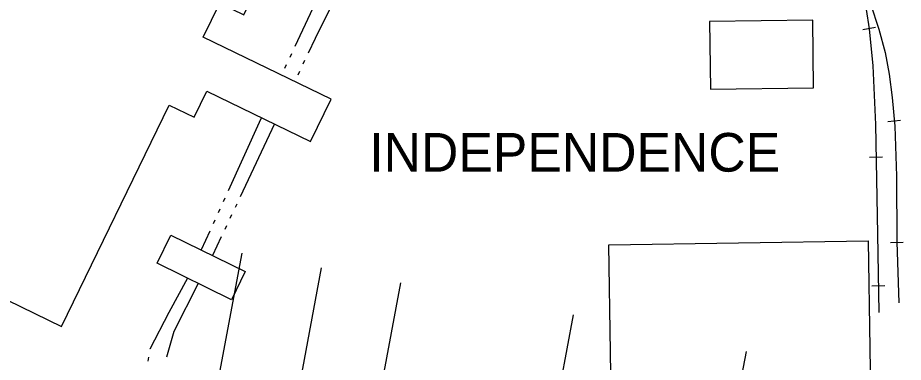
# Model space of a CAD drawing. Extents: x -25029 to 2274964, y -81170 to 687028.
# Drawn here: x -6125 to -5438, y -66014 to -65746 of the extents above; entities that cross this region are included whole.
import ezdxf

# ---------------------------------------------------------------- set-up
doc = ezdxf.new("R2010")
doc.units = 0
for name, color, linetype in [('BD_X_Canopy', 7, 'Continuous'), ('BLDG', 7, 'Continuous'), ('BRIDGE', 7, 'Continuous'), ('CITY-NAME', 7, 'Continuous'), ('RR', 7, 'Continuous'), ('TR_Turning_Path1', 7, 'Continuous'), ('WATER', 7, 'Continuous')]:
    doc.layers.add(name, color=color, linetype=linetype)

msp = doc.modelspace()

# ---------------------------------------------------------------- linework, layer by layer
at = {"layer": 'BD_X_Canopy'}
for p, q in [((-6013.27, -66266.31), (-5950.67, -65929.34)), ((-5951.75, -66277.75), (-5889.14, -65940.78)), ((-5890.22, -66289.19), (-5827.62, -65952.21)), ((-5756.09, -66314.07), (-5693.49, -65977.12))]:
    msp.add_line(p, q, dxfattribs=at)
at = {"layer": 'BLDG'}
for points in [[(-6090.73, -65986.09), (-6007.19, -65814.3), (-5987.85, -65823.7), (-5977.96, -65803.38), (-5897.49, -65842.51), (-5881.58, -65809.79), (-5980.73, -65761.57), (-5967.91, -65735.22), (-5949.36, -65744.24), (-5936.78, -65718.36), (-5956.11, -65708.96), (-5859.01, -65509.31), (-5928.1, -65475.71), (-5941.2, -65502.64), (-5964.09, -65491.51), (-5950.98, -65464.53), (-6027.49, -65427.32), (-6040.7, -65454.48), (-6052.09, -65448.94), (-6270.74, -65898.54)], [(-5587.38, -65801.96), (-5507.31, -65800.9), (-5508.01, -65748.34), (-5588.08, -65749.4)], [(-5464.9, -65919.57), (-5461.02, -66169.84), (-5662.41, -66172.96), (-5666.28, -65922.69)]]:
    msp.add_lwpolyline(points, close=True, dxfattribs=at)
at = {"layer": 'BRIDGE'}
msp.add_lwpolyline([(-6005.77, -65915.18), (-5948.18, -65943.59), (-5958.94, -65965.4), (-6016.53, -65937)], close=True, dxfattribs=at)
at = {"layer": 'RR'}
for p, q in [((-5469.15, -65755.55), (-5459.29, -65753.89)), ((-5449.78, -65826.93), (-5439.82, -65826.06)), ((-5463.92, -65854.64), (-5453.92, -65854.44)), ((-5447.76, -65920.93), (-5437.77, -65920.6)), ((-5462.13, -65954.6), (-5452.13, -65954.45))]:
    msp.add_line(p, q, dxfattribs=at)
for points in [[(-5509.4, -65612.28), (-5501.45, -65629.95), (-5492.99, -65649.66), (-5485.66, -65667.72), (-5479.77, -65686.65), (-5474.44, -65706.99), (-5470.36, -65723.98), (-5466.67, -65740.15), (-5464.18, -65754.94), (-5461.44, -65783.88), (-5459.43, -65829.39), (-5457.71, -65914.54), (-5456.83, -65975.4)], [(-5479.07, -65689.92), (-5470.58, -65712.22), (-5463.27, -65735.58), (-5456.64, -65755.33), (-5451.89, -65773.49), (-5448.62, -65790.34), (-5446.39, -65808.39), (-5444.43, -65830.72), (-5442.93, -65869.56), (-5442.78, -65920.48), (-5441.21, -65967.89)]]:
    msp.add_lwpolyline(points, dxfattribs=at)
at = {"layer": 'TR_Turning_Path1'}
msp.add_line((-5565.71, -66039.44), (-5559.35, -66005.51), dxfattribs=at)
at = {"layer": 'WATER'}
for p, q in [((-5883.14, -65712.23), (-5909.67, -65768.81)), ((-5912.33, -65774.47), (-5913.65, -65777.3)), ((-5902.16, -65779.64), (-5903.49, -65782.47)), ((-5916.31, -65782.96), (-5917.63, -65785.79)), ((-5906.16, -65788.12), (-5907.49, -65790.95)), ((-5925.42, -65828.93), (-5952.1, -65885.45)), ((-5964.06, -65886.56), (-5965.35, -65889.41)), ((-5954.77, -65891.1), (-5956.1, -65893.93)), ((-5967.94, -65895.09), (-5969.23, -65897.94)), ((-5971.82, -65903.63), (-5973.11, -65906.47)), ((-5958.77, -65899.58), (-5960.1, -65902.41)), ((-5975.7, -65912.16), (-5982.33, -65926.74)), ((-5962.77, -65908.06), (-5964.11, -65910.88)), ((-5966.77, -65916.54), (-5973.62, -65931.04)), ((-6023.16, -66010.05), (-6023.65, -66013.14))]:
    msp.add_line(p, q, dxfattribs=at)
for points in [[(-5872.03, -65717.85), (-5894.04, -65762.45), (-5899.49, -65773.99)], [(-5935.55, -65824), (-5937.36, -65827.86), (-5961.47, -65880.87)], [(-5993.04, -65948.59), (-6007.42, -65975.28), (-6022.16, -66003.84), (-6022.17, -66003.88)], [(-5984.56, -65952.77), (-6003.51, -65990.04), (-6009.2, -66009.93)]]:
    msp.add_lwpolyline(points, dxfattribs=at)

# ---------------------------------------------------------------- texts
at = {"layer": 'CITY-NAME'}
msp.add_text('INDEPENDENCE', height=30, dxfattribs=at).set_placement((-5852, -65865.96))

doc.saveas('drawing.dxf')
